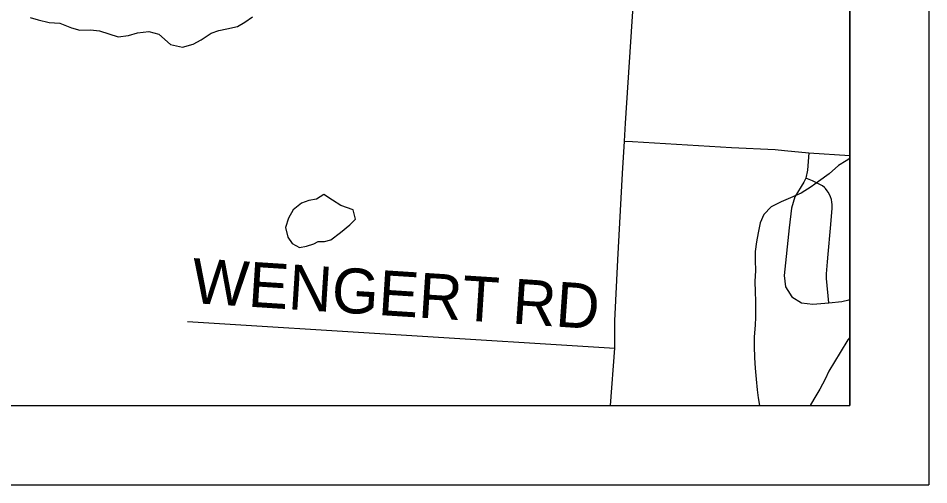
# Model space of a CAD drawing. Extents: x 208586767.6 to 208586821.4, y -134301046.9 to -134301022.9.
# Drawn here: x 208586783.778 to 208586784.928, y -134301030.941 to -134301030.351 of the extents above; entities that cross this region are included whole.
import ezdxf

# ---------------------------------------------------------------- set-up
doc = ezdxf.new("R2010")
doc.units = 0
for name, color, linetype in [('GM_X_Corporation', 7, 'Continuous'), ('GM_X_County_Road', 7, 'Continuous'), ('GM_X_Minor_Lake', 7, 'Continuous'), ('GM_X_Minor_River', 7, 'Continuous'), ('GM_X_Township_Road', 7, 'Continuous'), ('GM_X_Township_Road_Text', 7, 'Continuous'), ('SH_Data', 7, 'Continuous')]:
    doc.layers.add(name, color=color, linetype=linetype)

msp = doc.modelspace()

# ---------------------------------------------------------------- linework, layer by layer
at = {"layer": 'GM_X_Corporation'}
msp.add_lwpolyline([(208586780.4561, -134301030.8407), (208586784.8283, -134301030.8407), (208586784.8283, -134301027.3051), (208586784.2616, -134301027.2694), (208586783.9036, -134301027.2474), (208586783.5221, -134301027.2233), (208586782.8221, -134301027.178), (208586782.72, -134301027.1729), (208586782.648, -134301027.1691), (208586782.6378, -134301027.1684), (208586782.6086, -134301027.1669), (208586782.1685, -134301027.1422), (208586781.98, -134301027.1295), (208586781.8736, -134301027.1231), (208586781.8549, -134301027.122), (208586781.8329, -134301027.1207), (208586781.7344, -134301027.1148), (208586781.7056, -134301027.1139), (208586781.6677, -134301027.1118), (208586781.2713, -134301027.0897)], dxfattribs=at)
at = {"layer": 'GM_X_County_Road'}
msp.add_lwpolyline([(208586784.5262, -134301030.8407), (208586784.5315, -134301030.7681), (208586784.5315, -134301030.7336), (208586784.5353, -134301030.6564), (208586784.5412, -134301030.5475), (208586784.5437, -134301030.5064), (208586784.5449, -134301030.4836), (208586784.555, -134301030.3295)], dxfattribs=at)
at = {"layer": 'GM_X_Minor_Lake'}
for points in [[(208586784.125, -134301030.5934), (208586784.1192, -134301030.6036), (208586784.1157, -134301030.6157), (208586784.1183, -134301030.6279), (208586784.124, -134301030.6359), (208586784.133, -134301030.6409), (208586784.1422, -134301030.639), (208586784.1513, -134301030.6361), (208586784.157, -134301030.6334), (208586784.165, -134301030.6331), (208586784.1726, -134301030.6313), (208586784.1848, -134301030.6218), (208586784.1966, -134301030.612), (208586784.2039, -134301030.6049), (208586784.2009, -134301030.5931), (208586784.1854, -134301030.5877), (208586784.1748, -134301030.5812), (208586784.1638, -134301030.5739), (208586784.1547, -134301030.5799), (208586784.1452, -134301030.5814), (208586784.1357, -134301030.5847)], [(208586784.125, -134301030.5934), (208586784.1192, -134301030.6036), (208586784.1157, -134301030.6157), (208586784.1183, -134301030.6279), (208586784.124, -134301030.6359), (208586784.133, -134301030.6409), (208586784.1422, -134301030.639), (208586784.1513, -134301030.6361), (208586784.157, -134301030.6334), (208586784.165, -134301030.6331), (208586784.1726, -134301030.6313), (208586784.1848, -134301030.6218), (208586784.1966, -134301030.612), (208586784.2039, -134301030.6049), (208586784.2009, -134301030.5931), (208586784.1854, -134301030.5877), (208586784.1748, -134301030.5812), (208586784.1638, -134301030.5739), (208586784.1547, -134301030.5799), (208586784.1452, -134301030.5814), (208586784.1357, -134301030.5847)], [(208586784.1357, -134301030.5847), (208586784.125, -134301030.5934)], [(208586784.1357, -134301030.5847), (208586784.125, -134301030.5934)]]:
    msp.add_lwpolyline(points, dxfattribs=at)
at = {"layer": 'GM_X_Minor_River'}
for points in [[(208586783.7929, -134301030.3501), (208586783.8031, -134301030.3532), (208586783.8171, -134301030.3563), (208586783.8304, -134301030.3575), (208586783.8452, -134301030.3633), (208586783.8558, -134301030.366), (208586783.8691, -134301030.3657), (208586783.8805, -134301030.3669), (208586783.9039, -134301030.3746), (208586783.9172, -134301030.3728), (208586783.9286, -134301030.3695), (208586783.9427, -134301030.3677), (208586783.9556, -134301030.3711), (208586783.9703, -134301030.3841), (208586783.9855, -134301030.3876), (208586783.9988, -134301030.3839), (208586784.0091, -134301030.3783), (208586784.0216, -134301030.37), (208586784.0311, -134301030.3667), (208586784.0414, -134301030.3645), (208586784.0547, -134301030.3615), (208586784.0642, -134301030.3562), (208586784.0738, -134301030.3491)], [(208586784.8283, -134301030.5285), (208586784.8237, -134301030.5312), (208586784.8142, -134301030.5372), (208586784.8024, -134301030.5477), (208586784.789, -134301030.5575), (208586784.7795, -134301030.5643), (208586784.7669, -134301030.5722), (208586784.7536, -134301030.5782), (208586784.7418, -134301030.583), (208586784.7292, -134301030.5894), (208586784.7197, -134301030.5992), (208586784.7151, -134301030.6098), (208586784.7127, -134301030.6223), (208586784.7107, -134301030.6337), (208586784.7091, -134301030.6458), (208586784.7087, -134301030.6568), (208586784.7094, -134301030.6705), (208586784.7085, -134301030.6834), (208586784.7088, -134301030.6974), (208586784.7095, -134301030.7084), (208586784.7094, -134301030.7289), (208586784.7089, -134301030.7388), (208586784.7077, -134301030.7536), (208586784.7076, -134301030.7657), (208586784.7079, -134301030.7802), (208586784.709, -134301030.7934), (208586784.71, -134301030.8071), (208586784.7115, -134301030.8208), (208586784.7129, -134301030.8307), (208586784.7142, -134301030.8407)], [(208586784.8283, -134301030.7547), (208586784.8261, -134301030.7577), (208586784.8165, -134301030.7736), (208586784.8019, -134301030.797), (208586784.7973, -134301030.8073), (208586784.7908, -134301030.8197), (208586784.7831, -134301030.8326), (208586784.7784, -134301030.8407)]]:
    msp.add_lwpolyline(points, dxfattribs=at)
at = {"layer": 'GM_X_Township_Road'}
for p, q in [((208586784.5437, -134301030.5064), (208586784.5538, -134301030.507)), ((208586783.9915, -134301030.7343), (208586784.5315, -134301030.7681))]:
    msp.add_line(p, q, dxfattribs=at)
for points in [[(208586784.5538, -134301030.507), (208586784.679, -134301030.5146), (208586784.734, -134301030.5169), (208586784.7461, -134301030.5181)], [(208586784.7765, -134301030.5213), (208586784.775, -134301030.5432), (208586784.7728, -134301030.5534), (208586784.7704, -134301030.5583), (208586784.7592, -134301030.5769), (208586784.7547, -134301030.591), (208586784.752, -134301030.6158), (208586784.7457, -134301030.6762), (208586784.7474, -134301030.6907), (208586784.7502, -134301030.6951)], [(208586784.7461, -134301030.5181), (208586784.7765, -134301030.5213), (208586784.8283, -134301030.5246)], [(208586784.8019, -134301030.7107), (208586784.7991, -134301030.6799), (208586784.799, -134301030.6771), (208586784.799, -134301030.6742), (208586784.7993, -134301030.6692), (208586784.8002, -134301030.6591), (208586784.8011, -134301030.6493), (208586784.804, -134301030.6164), (208586784.8062, -134301030.5917), (208586784.8063, -134301030.5866), (208586784.8059, -134301030.5836), (208586784.8052, -134301030.5801), (208586784.8041, -134301030.577), (208586784.8027, -134301030.5737), (208586784.8012, -134301030.571), (208586784.7998, -134301030.5691), (208586784.7976, -134301030.5664), (208586784.7963, -134301030.565), (208586784.7939, -134301030.5629), (208586784.7915, -134301030.5617), (208586784.7815, -134301030.5567), (208586784.7728, -134301030.5534)], [(208586784.7502, -134301030.6951), (208586784.7551, -134301030.703), (208586784.7673, -134301030.7108), (208586784.7818, -134301030.7126), (208586784.8019, -134301030.7107), (208586784.8182, -134301030.7092), (208586784.8271, -134301030.7071), (208586784.8283, -134301030.7066)]]:
    msp.add_lwpolyline(points, dxfattribs=at)
at = {"layer": 'SH_Data'}
for p, q in [((208586784.9283, -134301023.9407), (208586784.9283, -134301030.9407)), ((208586784.8283, -134301024.0407), (208586784.8283, -134301030.8407)), ((208586778.0283, -134301030.8407), (208586784.8283, -134301030.8407)), ((208586777.9283, -134301030.9407), (208586784.9283, -134301030.9407))]:
    msp.add_line(p, q, dxfattribs=at)

# ---------------------------------------------------------------- texts
at = {"layer": 'GM_X_Township_Road_Text'}
for s, rotation, p in [('WENGERT', 356.3357, (208586783.9958, -134301030.7109)), ('RD', 356.0533, (208586784.4009, -134301030.7368))]:
    msp.add_text(s, height=0.05682, rotation=rotation, dxfattribs=at).set_placement(p)

doc.saveas('drawing.dxf')
